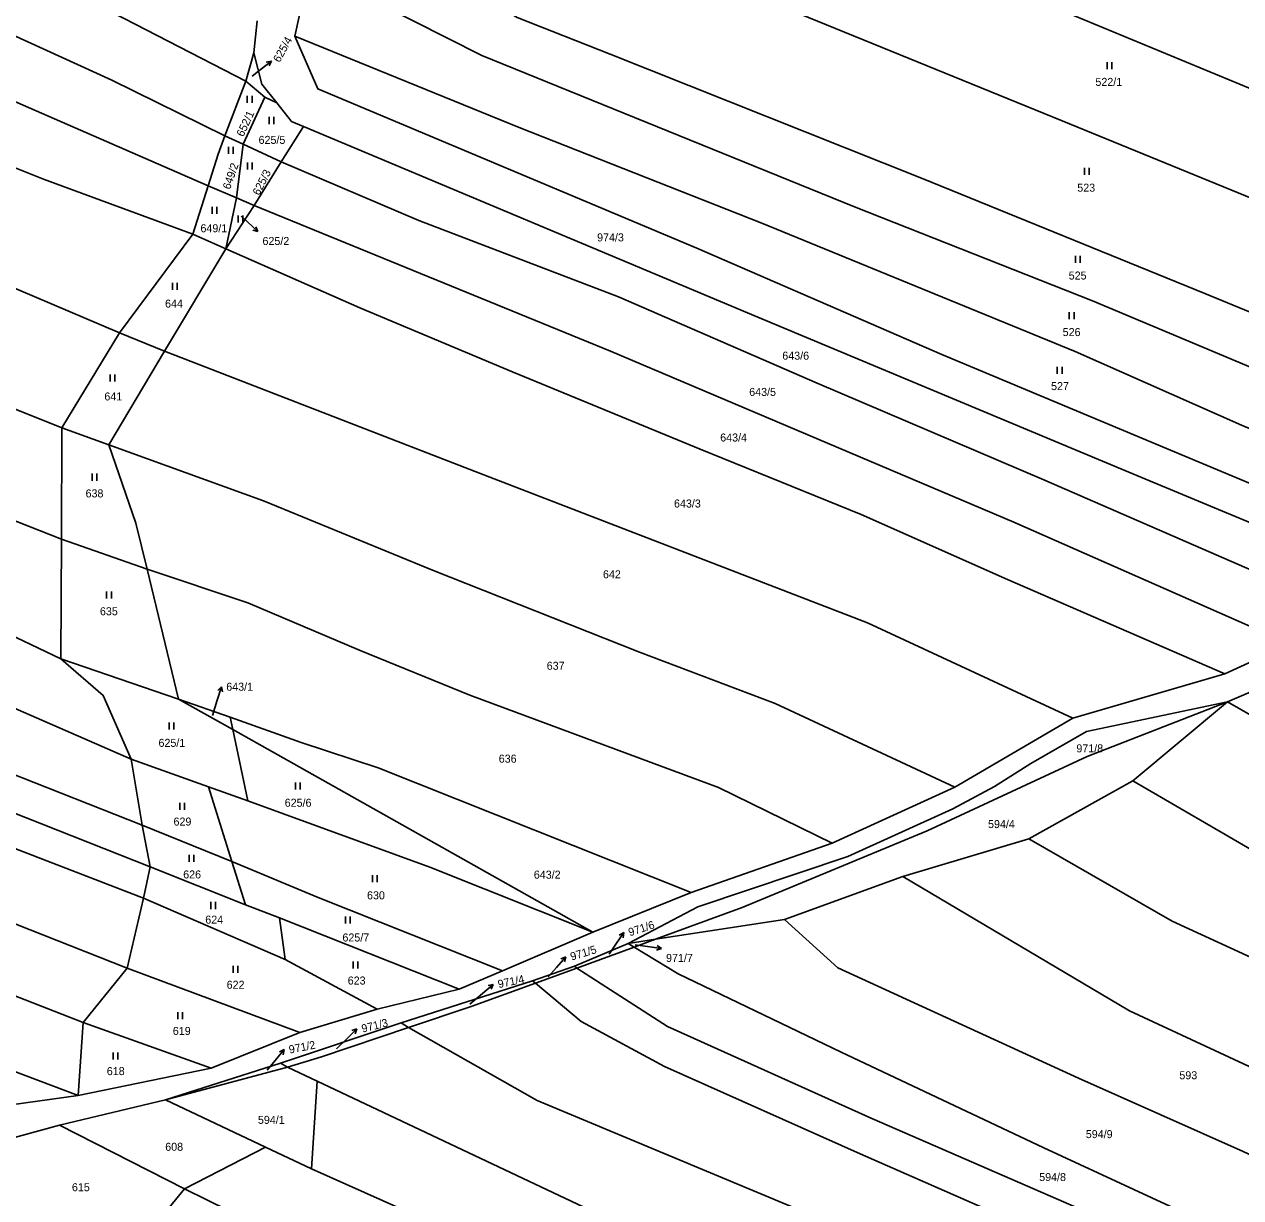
# Model space of a CAD drawing. Extents: x -7476540 to -746055, y -11317203 to -1129777.
# Drawn here: x -748699.3 to -748441, y -1131012.8 to -1130763.6 of the extents above; entities that cross this region are included whole.
import ezdxf

# ---------------------------------------------------------------- set-up
doc = ezdxf.new("R2010")
doc.units = 0
for name, color, linetype in [('Hranice parcel', 7, 'Continuous'), ('Parcelní čísla', 7, 'Continuous'), ('Pop  PČ popisy', 7, 'Continuous'), ('Značky kultur', 7, 'Continuous')]:
    doc.layers.add(name, color=color, linetype=linetype)

msp = doc.modelspace()

# ---------------------------------------------------------------- linework, layer by layer
at = {"layer": 'Hranice parcel'}
for p, q in [((-748641.83, -1130766.14), (-748638.72, -1130751.72)), ((-748649.86, -1130762.87), (-748650.55, -1130769.73)), ((-748650.55, -1130769.73), (-748652.25, -1130775.75)), ((-748652.25, -1130775.75), (-748656.74, -1130787.3)), ((-748652.25, -1130775.75), (-748648.22, -1130779.11)), ((-748648.22, -1130779.11), (-748652.83, -1130789.11)), ((-748648.22, -1130779.11), (-748645.64, -1130780.35)), ((-748652.83, -1130789.11), (-748656.74, -1130787.3)), ((-748644.72, -1130792.86), (-748640.02, -1130785.32)), ((-748652.83, -1130789.11), (-748654.25, -1130800.53)), ((-748644.72, -1130792.86), (-748652.83, -1130789.11)), ((-748650.5, -1130802.12), (-748644.72, -1130792.86)), ((-748663.47, -1130808.22), (-748660.26, -1130797.97)), ((-748654.25, -1130800.53), (-748660.26, -1130797.97)), ((-748654.25, -1130800.53), (-748656.51, -1130811.34)), ((-748656.51, -1130811.34), (-748650.5, -1130802.12)), ((-748650.5, -1130802.12), (-748654.25, -1130800.53)), ((-748663.47, -1130808.22), (-748679.08, -1130829.15)), ((-748656.51, -1130811.34), (-748663.47, -1130808.22)), ((-748656.51, -1130811.34), (-748669.5, -1130833.07)), ((-748691.29, -1130849.38), (-748679.08, -1130829.15)), ((-748669.5, -1130833.07), (-748679.08, -1130829.15)), ((-748681.37, -1130852.94), (-748669.5, -1130833.07)), ((-748691.29, -1130849.38), (-748691.38, -1130873.01)), ((-748681.37, -1130852.94), (-748691.29, -1130849.38)), ((-748691.56, -1130898.44), (-748691.38, -1130873.01)), ((-748673.21, -1130879.38), (-748691.38, -1130873.01)), ((-748666.52, -1130906.98), (-748673.21, -1130879.38)), ((-748444.32, -1130901.6), (-748430.56, -1130895.23)), ((-748666.52, -1130906.98), (-748691.56, -1130898.44)), ((-748476.62, -1130910.98), (-748444.32, -1130901.6)), ((-748655.04, -1130913.44), (-748666.52, -1130906.98)), ((-748666.52, -1130906.98), (-748655.57, -1130910.8)), ((-748443.77, -1130907.57), (-748463.91, -1130924.32)), ((-748655.04, -1130913.44), (-748655.57, -1130910.8)), ((-748501.67, -1130925.66), (-748476.62, -1130910.98)), ((-748651.83, -1130928.55), (-748655.04, -1130913.44)), ((-748578.54, -1130956.49), (-748655.04, -1130913.44)), ((-748676.59, -1130919.71), (-748660.16, -1130925.62)), ((-748674.28, -1130933.73), (-748676.59, -1130919.71)), ((-748660.16, -1130925.62), (-748651.83, -1130928.55)), ((-748655.19, -1130941.48), (-748660.16, -1130925.62)), ((-748527.72, -1130937.53), (-748501.67, -1130925.66)), ((-748463.91, -1130924.32), (-748485.95, -1130936.62)), ((-748655.19, -1130941.48), (-748674.28, -1130933.73)), ((-748674.28, -1130933.73), (-748672.59, -1130942.59)), ((-748485.95, -1130936.62), (-748512.7, -1130944.65)), ((-748557.64, -1130948.06), (-748527.72, -1130937.53)), ((-748655.19, -1130941.48), (-748652.32, -1130950.63)), ((-748672.59, -1130942.59), (-748673.99, -1130949.21)), ((-748652.32, -1130950.63), (-748672.59, -1130942.59)), ((-748512.7, -1130944.65), (-748537.89, -1130953.74)), ((-748677.43, -1130964.14), (-748673.99, -1130949.21)), ((-748643.86, -1130962.26), (-748673.99, -1130949.21)), ((-748578.54, -1130956.49), (-748557.64, -1130948.06)), ((-748645.13, -1130953.44), (-748652.32, -1130950.63)), ((-748645.13, -1130953.44), (-748643.86, -1130962.26)), ((-748606.96, -1130968.54), (-748645.13, -1130953.44)), ((-748565.28, -1130957.97), (-748537.89, -1130953.74)), ((-748597.75, -1130964.64), (-748578.54, -1130956.49)), ((-748582.43, -1130963.71), (-748571.03, -1130958.84)), ((-748569.8, -1130959.62), (-748581.99, -1130964.07)), ((-748565.28, -1130957.97), (-748571.03, -1130958.84)), ((-748569.8, -1130959.62), (-748571.03, -1130958.84)), ((-748565.28, -1130957.97), (-748569.8, -1130959.62)), ((-748624.37, -1130972.78), (-748643.86, -1130962.26)), ((-748677.43, -1130964.14), (-748686.82, -1130975.66)), ((-748640.75, -1130977.76), (-748677.43, -1130964.14)), ((-748606.96, -1130968.54), (-748597.75, -1130964.64)), ((-748591.34, -1130966.78), (-748582.43, -1130963.71)), ((-748581.99, -1130964.07), (-748590.75, -1130967.27)), ((-748581.99, -1130964.07), (-748582.43, -1130963.71)), ((-748619.29, -1130975.71), (-748591.34, -1130966.78)), ((-748590.75, -1130967.27), (-748591.34, -1130966.78)), ((-748624.37, -1130972.78), (-748606.96, -1130968.54)), ((-748640.75, -1130977.76), (-748624.37, -1130972.78)), ((-748687.86, -1130991.16), (-748686.82, -1130975.66)), ((-748659.6, -1130985.35), (-748686.82, -1130975.66)), ((-748644.89, -1130984.3), (-748619.29, -1130975.71)), ((-748617.7, -1130976.74), (-748619.29, -1130975.71)), ((-748659.6, -1130985.35), (-748640.75, -1130977.76)), ((-748687.86, -1130991.16), (-748659.6, -1130985.35)), ((-748669.28, -1130992.07), (-748644.89, -1130984.3)), ((-748643.37, -1130985.15), (-748669.28, -1130992.07)), ((-748643.37, -1130985.15), (-748644.89, -1130984.3)), ((-748637.1, -1130988.07), (-748643.37, -1130985.15)), ((-748638.28, -1131006.71), (-748637.1, -1130988.07)), ((-748722.45, -1130995.95), (-748687.86, -1130991.16)), ((-748669.28, -1130992.07), (-748691.81, -1130997.44)), ((-748669.28, -1130992.07), (-748648.09, -1131002.15)), ((-748691.81, -1130997.44), (-748665.29, -1131010.97)), ((-748665.29, -1131010.97), (-748648.09, -1131002.15)), ((-748648.09, -1131002.15), (-748638.28, -1131006.71)), ((-748638.28, -1131006.71), (-748611.82, -1131018.52)), ((-748665.29, -1131010.97), (-748675.21, -1131023.11))]:
    msp.add_line(p, q, dxfattribs=at)
for points in [[(-748652.25, -1130775.75), (-748685.2, -1130758.76), (-748723.6, -1130742.09), (-748761.55, -1130723.94), (-748816.32, -1130700.21), (-748847.4, -1130686.03), (-748860.58, -1130679.64)], [(-748656.74, -1130787.3), (-748680.72, -1130775.54), (-748712.39, -1130761.05), (-748780.75, -1130728.31), (-748831.33, -1130705.07), (-748858.25, -1130692.59)], [(-748600.62, -1130708.93), (-748572.02, -1130722.05), (-748553.57, -1130730.11), (-748529.63, -1130739.69), (-748429.06, -1130781.38), (-748394.01, -1130795.35), (-748336, -1130816.73)], [(-748855.58, -1130710.12), (-748821.23, -1130726.15), (-748767.45, -1130750.32), (-748729.5, -1130767.78), (-748660.26, -1130797.97)], [(-748663.47, -1130808.22), (-748695.21, -1130796.54), (-748721.13, -1130786.22), (-748753.25, -1130772.41), (-748790.9, -1130755.21), (-748826.39, -1130739.6), (-748853.82, -1130727.9)], [(-748609.37, -1130729.04), (-748586.47, -1130739.97), (-748565.25, -1130748.92), (-748478.86, -1130784.11), (-748430.59, -1130803.91), (-748354.99, -1130834.29)], [(-748617.75, -1130748.36), (-748594.66, -1130762.19), (-748574.85, -1130769.98), (-748508.41, -1130796.48), (-748448.56, -1130820.81), (-748391.34, -1130844.41), (-748350.77, -1130860.5)], [(-748638.72, -1130751.72), (-748602.16, -1130770.3), (-748522.97, -1130802.41), (-748472.42, -1130822.39), (-748429.14, -1130840.54), (-748407.16, -1130849.74), (-748367.71, -1130867.32)], [(-748641.83, -1130766.14), (-748594.17, -1130785.58), (-748542.67, -1130805.9), (-748476.15, -1130833.14), (-748440.81, -1130848.76), (-748384.89, -1130872.51)], [(-748384.89, -1130872.51), (-748392.79, -1130874.89), (-748407.29, -1130874.39), (-748504.41, -1130833.78), (-748556.44, -1130811.2), (-748636.94, -1130777.36), (-748641.83, -1130766.14)], [(-748650.55, -1130769.73), (-748648.82, -1130776.37), (-748645.64, -1130780.35)], [(-748645.64, -1130780.35), (-748642.52, -1130784.27), (-748640.02, -1130785.32)], [(-748679.08, -1130829.15), (-748725.39, -1130809.48), (-748784.49, -1130785.99)], [(-748660.26, -1130797.97), (-748658.12, -1130791.2), (-748656.74, -1130787.3)], [(-748640.02, -1130785.32), (-748543.51, -1130825.81), (-748464.71, -1130858.77), (-748407.23, -1130882.69)], [(-748417.27, -1130888.93), (-748482.75, -1130860.42), (-748530.93, -1130839.89), (-748573.14, -1130821.5), (-748615.5, -1130805.28), (-748644.72, -1130792.86)], [(-748430.56, -1130895.23), (-748489.17, -1130869.4), (-748574.8, -1130833.09), (-748650.5, -1130802.12)], [(-748444.32, -1130901.6), (-748490.53, -1130881.55), (-748521.6, -1130867.76), (-748555.74, -1130853.87), (-748595.49, -1130837.5), (-748628.03, -1130823.85), (-748656.51, -1130811.34)], [(-748691.29, -1130849.38), (-748752.74, -1130824.68), (-748778.58, -1130815.45)], [(-748476.62, -1130910.98), (-748520.26, -1130890.78), (-748603.55, -1130858.65), (-748669.5, -1130833.07)], [(-748691.38, -1130873.01), (-748733.87, -1130856.25), (-748780.28, -1130837.27)], [(-748681.37, -1130852.94), (-748675.59, -1130869.57), (-748673.21, -1130879.38)], [(-748501.67, -1130925.66), (-748539.81, -1130907.88), (-748568.68, -1130897.02), (-748612.61, -1130879.56), (-748648.46, -1130864.82), (-748681.37, -1130852.94)], [(-748691.56, -1130898.44), (-748724.77, -1130882.55), (-748750.23, -1130872.02), (-748786.7, -1130856.35)], [(-748676.59, -1130919.71), (-748742.5, -1130891), (-748791.23, -1130869.37)], [(-748527.72, -1130937.53), (-748551.88, -1130925.74), (-748604.69, -1130906.09), (-748627.96, -1130896.65), (-748651.82, -1130886.51), (-748673.21, -1130879.38)], [(-748674.28, -1130933.73), (-748702.92, -1130922.4), (-748733.51, -1130909.72), (-748760.2, -1130899.08), (-748798.57, -1130882.46)], [(-748672.59, -1130942.59), (-748728.61, -1130920.39), (-748772.9, -1130902.53), (-748801.95, -1130888.88)], [(-748673.99, -1130949.21), (-748734.35, -1130925.92), (-748775.96, -1130909.83), (-748805.64, -1130895.06)], [(-748418.37, -1130896.38), (-748428.88, -1130901.17), (-748443.77, -1130907.57)], [(-748691.56, -1130898.44), (-748682.52, -1130906.16), (-748676.59, -1130919.71)], [(-748677.43, -1130964.14), (-748742.72, -1130938.33), (-748781.18, -1130922.64), (-748812.83, -1130907.88)], [(-748571.03, -1130958.84), (-748556.25, -1130951.09), (-748524.38, -1130940.39), (-748502.11, -1130930.25), (-748493.27, -1130925.55), (-748485.55, -1130920.61), (-748473.74, -1130913.87), (-748443.77, -1130907.57)], [(-748443.77, -1130907.57), (-748473.57, -1130919.12), (-748507.59, -1130934.95), (-748546.84, -1130951.23), (-748565.28, -1130957.97)], [(-748443.77, -1130907.57), (-748419.77, -1130921.28), (-748359.61, -1130948.54), (-748326.95, -1130962.5)], [(-748655.57, -1130910.8), (-748640.51, -1130916.19), (-748624.12, -1130921.59), (-748557.64, -1130948.06)], [(-748686.82, -1130975.66), (-748760.05, -1130947.07), (-748824.49, -1130922.2)], [(-748463.91, -1130924.32), (-748437.34, -1130939.73), (-748391.2, -1130959.35), (-748362.89, -1130972.76), (-748338.46, -1130984.21)], [(-748651.83, -1130928.55), (-748613.14, -1130942.66), (-748578.54, -1130956.49)], [(-748687.86, -1130991.16), (-748755.34, -1130965.63), (-748835.48, -1130935.7)], [(-748485.95, -1130936.62), (-748455.56, -1130954.14), (-748433.55, -1130964.26), (-748406.22, -1130976.23), (-748360.19, -1130998.63)], [(-748597.75, -1130964.64), (-748636.89, -1130949.07), (-748655.19, -1130941.48)], [(-748512.7, -1130944.65), (-748464.62, -1130973.2), (-748424.22, -1130991.94), (-748412.15, -1130998.16), (-748403.69, -1131002.73), (-748383.15, -1131012.7)], [(-748537.89, -1130953.74), (-748526.55, -1130964.01), (-748475.44, -1130987.44), (-748440.48, -1131003.02), (-748392.16, -1131025.73)], [(-748401.59, -1131039.86), (-748482.79, -1131002.25), (-748525.81, -1130981.98), (-748560.43, -1130965.34), (-748569.8, -1130959.62)], [(-748408.58, -1131046.09), (-748444.76, -1131028.43), (-748487.86, -1131009.7), (-748519.33, -1130996.05), (-748562.72, -1130976.46), (-748581.99, -1130964.07)], [(-748590.75, -1130967.27), (-748604.42, -1130972.26), (-748617.7, -1130976.74)], [(-748417.45, -1131050.74), (-748429.46, -1131045.22), (-748443.17, -1131038.57), (-748447.76, -1131036), (-748521.8, -1131003.51), (-748563.34, -1130984.99), (-748581.03, -1130975.42), (-748590.75, -1130967.27)], [(-748617.7, -1130976.74), (-748636.18, -1130982.97), (-748643.37, -1130985.15)], [(-748433.86, -1131062.5), (-748469.72, -1131045.54), (-748503.59, -1131029.98), (-748535.57, -1131015.06), (-748590.35, -1130992.22), (-748617.7, -1130976.74)], [(-748637.1, -1130988.07), (-748580.62, -1131014.77), (-748540.84, -1131031.61), (-748501.83, -1131050.32), (-748475.33, -1131062.6), (-748443.88, -1131076.03)], [(-748691.81, -1130997.44), (-748710.23, -1131002.5), (-748718.11, -1131005.41)], [(-748665.29, -1131010.97), (-748646.27, -1131020.35), (-748619.14, -1131033.17)]]:
    msp.add_lwpolyline(points, dxfattribs=at)
at = {"layer": 'Pop  PČ popisy'}
for p, q in [((-748649.19, -1130773.31), (-748646.83, -1130771.46)), ((-748646.83, -1130771.46), (-748647.92, -1130771.68)), ((-748646.83, -1130771.46), (-748647.31, -1130772.47)), ((-748650.91, -1130774.65), (-748649.19, -1130773.31)), ((-748653.26, -1130804.36), (-748651.91, -1130805.62)), ((-748651.91, -1130805.62), (-748649.71, -1130807.67)), ((-748649.71, -1130807.67), (-748650.79, -1130807.35)), ((-748649.71, -1130807.67), (-748650.11, -1130806.62)), ((-748658.31, -1130907.19), (-748657.38, -1130904.34)), ((-748657.38, -1130904.34), (-748658.17, -1130905.13)), ((-748657.38, -1130904.34), (-748657.22, -1130905.44)), ((-748659.35, -1130910.44), (-748658.31, -1130907.19)), ((-748573.65, -1130959.02), (-748571.97, -1130956.53)), ((-748571.97, -1130956.53), (-748572.95, -1130957.08)), ((-748571.97, -1130956.53), (-748572.12, -1130957.64)), ((-748575.07, -1130961.12), (-748573.65, -1130959.02)), ((-748569.54, -1130959.13), (-748566.98, -1130959.5)), ((-748566.98, -1130959.5), (-748564.01, -1130959.92)), ((-748564.01, -1130959.92), (-748565.07, -1130960.27)), ((-748564.01, -1130959.92), (-748564.93, -1130959.28)), ((-748586.29, -1130963.95), (-748584.32, -1130961.69)), ((-748584.32, -1130961.69), (-748585.36, -1130962.11)), ((-748584.32, -1130961.69), (-748584.6, -1130962.77)), ((-748588.06, -1130965.95), (-748586.29, -1130963.95)), ((-748602, -1130969.47), (-748599.7, -1130967.54)), ((-748599.7, -1130967.54), (-748600.79, -1130967.8)), ((-748599.7, -1130967.54), (-748600.15, -1130968.57)), ((-748604.67, -1130971.74), (-748602, -1130969.47)), ((-748630.8, -1130979.1), (-748628.68, -1130976.98)), ((-748628.68, -1130976.98), (-748629.74, -1130977.33)), ((-748628.68, -1130976.98), (-748629.03, -1130978.04)), ((-748633, -1130981.27), (-748630.8, -1130979.1)), ((-748646.02, -1130983.71), (-748644.09, -1130981.41)), ((-748644.09, -1130981.41), (-748645.12, -1130981.86)), ((-748644.09, -1130981.41), (-748644.35, -1130982.5)), ((-748647.75, -1130985.76), (-748646.02, -1130983.71))]:
    msp.add_line(p, q, dxfattribs=at)
at = {"layer": 'Značky kultur'}
for p, q in [((-748469.34, -1130773.17), (-748469.34, -1130771.67)), ((-748468.34, -1130773.17), (-748468.34, -1130771.67)), ((-748651.93, -1130780.34), (-748651.93, -1130778.84)), ((-748650.93, -1130780.34), (-748650.93, -1130778.84)), ((-748647.32, -1130784.82), (-748647.32, -1130783.32)), ((-748646.32, -1130784.82), (-748646.32, -1130783.32)), ((-748655.93, -1130791.13), (-748655.93, -1130789.63)), ((-748654.93, -1130791.13), (-748654.93, -1130789.63)), ((-748651.9, -1130794.49), (-748651.9, -1130792.99)), ((-748650.9, -1130794.49), (-748650.9, -1130792.99)), ((-748474.18, -1130795.64), (-748474.18, -1130794.14)), ((-748473.18, -1130795.64), (-748473.18, -1130794.14)), ((-748659.38, -1130803.9), (-748659.38, -1130802.4)), ((-748658.38, -1130803.9), (-748658.38, -1130802.4)), ((-748653.89, -1130805.73), (-748653.89, -1130804.23)), ((-748652.89, -1130805.73), (-748652.89, -1130804.23)), ((-748476.05, -1130814.29), (-748476.05, -1130812.79)), ((-748475.05, -1130814.29), (-748475.05, -1130812.79)), ((-748667.83, -1130820.02), (-748667.83, -1130818.52)), ((-748666.83, -1130820.02), (-748666.83, -1130818.52)), ((-748477.37, -1130826.25), (-748477.37, -1130824.75)), ((-748476.37, -1130826.25), (-748476.37, -1130824.75)), ((-748681.03, -1130839.49), (-748681.03, -1130837.99)), ((-748680.03, -1130839.49), (-748680.03, -1130837.99)), ((-748479.92, -1130837.9), (-748479.92, -1130836.4)), ((-748478.92, -1130837.9), (-748478.92, -1130836.4)), ((-748684.86, -1130860.57), (-748684.86, -1130859.07)), ((-748683.86, -1130860.57), (-748683.86, -1130859.07)), ((-748681.8, -1130885.6), (-748681.8, -1130884.1)), ((-748680.8, -1130885.6), (-748680.8, -1130884.1)), ((-748668.52, -1130913.4), (-748668.52, -1130911.9)), ((-748667.52, -1130913.4), (-748667.52, -1130911.9)), ((-748641.71, -1130926.15), (-748641.71, -1130924.65)), ((-748640.71, -1130926.15), (-748640.71, -1130924.65)), ((-748666.28, -1130930.46), (-748666.28, -1130928.96)), ((-748665.28, -1130930.46), (-748665.28, -1130928.96)), ((-748664.31, -1130941.51), (-748664.31, -1130940.01)), ((-748663.31, -1130941.51), (-748663.31, -1130940.01)), ((-748625.33, -1130945.86), (-748625.33, -1130944.36)), ((-748624.33, -1130945.86), (-748624.33, -1130944.36)), ((-748659.67, -1130951.55), (-748659.67, -1130950.05)), ((-748658.67, -1130951.55), (-748658.67, -1130950.05)), ((-748631.09, -1130954.6), (-748631.09, -1130953.1)), ((-748630.09, -1130954.6), (-748630.09, -1130953.1)), ((-748629.44, -1130964.17), (-748629.44, -1130962.67)), ((-748628.44, -1130964.17), (-748628.44, -1130962.67)), ((-748654.92, -1130965.12), (-748654.92, -1130963.62)), ((-748653.92, -1130965.12), (-748653.92, -1130963.62)), ((-748666.68, -1130974.92), (-748666.68, -1130973.42)), ((-748665.68, -1130974.92), (-748665.68, -1130973.42)), ((-748680.42, -1130983.52), (-748680.42, -1130982.02)), ((-748679.42, -1130983.52), (-748679.42, -1130982.02))]:
    msp.add_line(p, q, dxfattribs=at)

# ---------------------------------------------------------------- texts
at = {"layer": 'Parcelní čísla'}
for s, rotation, p in [('625/4', 61, (-748645.08, -1130771.88)), ('652/1', 65, (-748652.79, -1130787.66)), ('649/2', 71, (-748655.61, -1130798.83)), ('625/3', 63, (-748649.41, -1130800.11)), ('971/6', 18, (-748570.7, -1130957.35)), ('971/5', 17, (-748583.05, -1130962.51)), ('971/4', 12, (-748598.54, -1130968.35)), ('971/3', 14, (-748627.45, -1130977.81)), ('971/2', 11, (-748642.93, -1130982.25))]:
    msp.add_text(s, height=1.7, rotation=rotation, dxfattribs=at).set_placement(p)
for s, p in [('522/1', (-748471.83, -1130776.72)), ('625/5', (-748649.54, -1130789.04)), ('523', (-748475.68, -1130799.19)), ('649/1', (-748661.88, -1130807.81)), ('974/3', (-748577.65, -1130809.75)), ('625/2', (-748648.71, -1130810.51)), ('525', (-748477.5, -1130817.85)), ('644', (-748669.4, -1130823.81)), ('526', (-748478.78, -1130829.86)), ('643/6', (-748538.32, -1130834.87)), ('643/5', (-748545.35, -1130842.57)), ('527', (-748481.25, -1130841.33)), ('641', (-748682.29, -1130843.53)), ('643/4', (-748551.51, -1130852.25)), ('638', (-748686.28, -1130864.12)), ('643/3', (-748561.32, -1130866.27)), ('642', (-748576.41, -1130881.3)), ('635', (-748683.23, -1130889.15)), ('637', (-748588.35, -1130900.73)), ('643/1', (-748656.4, -1130905.18)), ('625/1', (-748670.79, -1130917.1)), ('636', (-748598.54, -1130920.46)), ('971/8', (-748475.87, -1130918.27)), ('625/6', (-748643.99, -1130929.82)), ('629', (-748667.6, -1130933.82)), ('594/4', (-748494.63, -1130934.35)), ('626', (-748665.55, -1130945.05)), ('643/2', (-748591.09, -1130945.09)), ('630', (-748626.51, -1130949.48)), ('624', (-748660.86, -1130954.65)), ('625/7', (-748631.73, -1130958.44)), ('971/7', (-748563.01, -1130962.78)), ('622', (-748656.32, -1130968.48)), ('623', (-748630.61, -1130967.58)), ('619', (-748667.75, -1130978.29)), ('618', (-748681.77, -1130986.82)), ('593', (-748454, -1130987.7)), ('594/1', (-748649.68, -1130997.17)), ('594/9', (-748473.87, -1131000.2)), ('608', (-748669.36, -1131002.89)), ('594/8', (-748483.77, -1131009.32)), ('615', (-748689.18, -1131011.48))]:
    msp.add_text(s, height=1.7, dxfattribs=at).set_placement(p)

doc.saveas('drawing.dxf')
